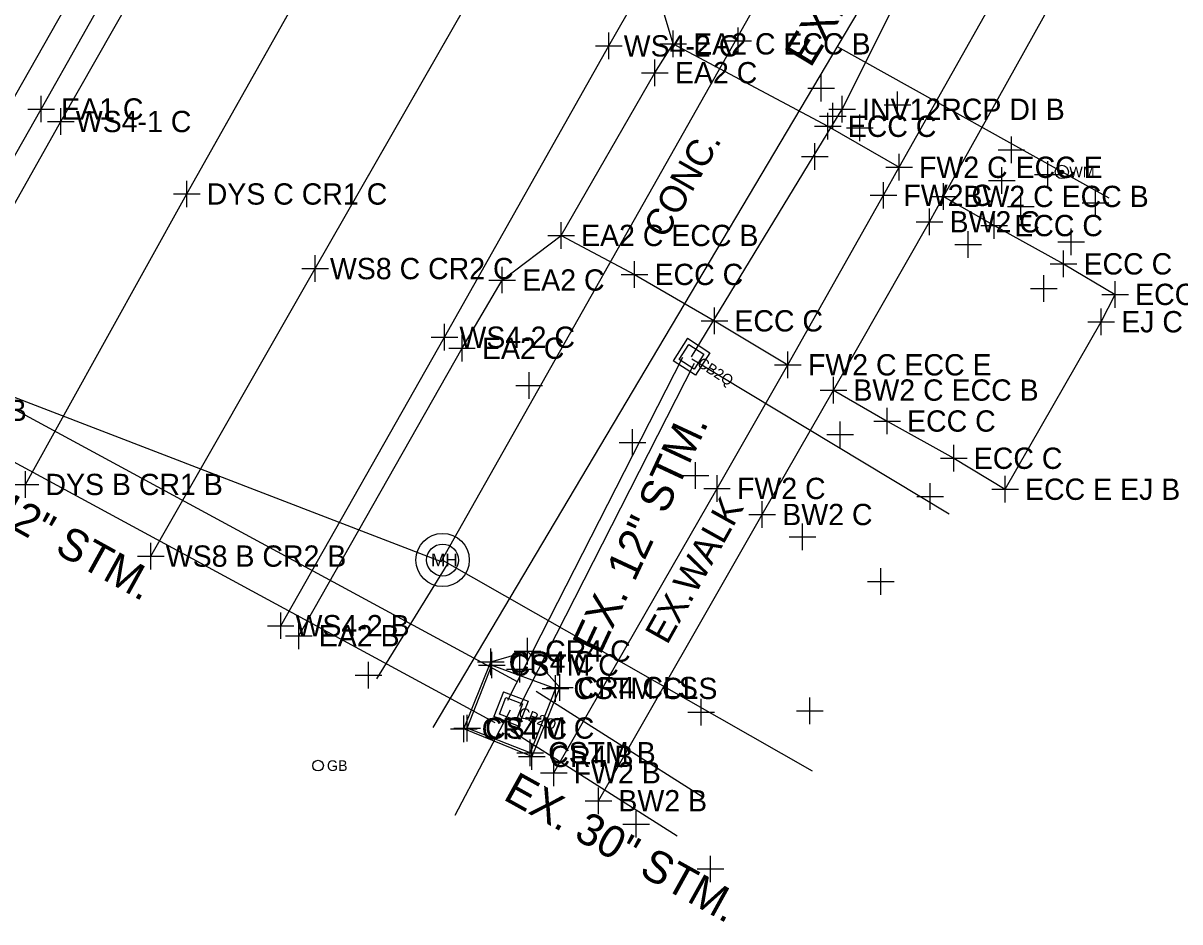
# Model space of a CAD drawing. Extents: x 1363693 to 1365209, y 422201 to 424153.
# Drawn here: x 1364063.7 to 1364150.5, y 422675.6 to 422743.1 of the extents above; entities that cross this region are included whole.
import ezdxf

# ---------------------------------------------------------------- set-up
doc = ezdxf.new("R2010")
doc.units = 0
for name, color, linetype in [('DR_X_Cells', 7, 'Continuous'), ('DR_X_Ditch', 7, 'Continuous'), ('DR_X_Storm_Sewer', 7, 'Continuous'), ('DR_X_Text', 7, 'Continuous'), ('O-ALGN-BASELINE-WERK-CL-RW', 7, 'Continuous'), ('O-ALGN-TEXT-BASELINE-WERK-CL-RW', 7, 'Continuous'), ('OWNERS', 7, 'Continuous'), ('PM_X_Channelizing_Line', 7, 'Continuous'), ('PM_X_CL_Double_Solid', 7, 'Continuous'), ('PM_X_Edge_Line', 7, 'Continuous'), ('PV_X_Driveway', 7, 'Continuous'), ('PV_X_Joint', 7, 'Continuous'), ('RD_X_Text', 7, 'Continuous'), ('SV_X_Original_Ground', 7, 'Continuous'), ('SV_X_Shot_Marker', 7, 'Continuous'), ('UT_X_Gas', 7, 'Continuous'), ('UT_X_Gas_Cells', 7, 'Continuous'), ('UT_X_Gas_Text', 7, 'Continuous'), ('UT_X_Sanitary_Line', 7, 'Continuous'), ('UT_X_Unknown_Cells', 7, 'Continuous'), ('UT_X_Water', 7, 'Continuous'), ('UT_X_Water_Text', 7, 'Continuous')]:
    doc.layers.add(name, color=color, linetype=linetype)

msp = doc.modelspace()

# ---------------------------------------------------------------- linework, layer by layer
at = {"layer": 'DR_X_Cells'}
for p, q in [((1364113.567, 422719.415), (1364112.486, 422717.732)), ((1364112.947, 422717.833), (1364113.668, 422718.954)), ((1364113.567, 422719.415), (1364115.25, 422718.334)), ((1364113.668, 422718.954), (1364114.789, 422718.233)), ((1364114.789, 422718.233), (1364114.068, 422717.112)), ((1364115.25, 422718.334), (1364114.169, 422716.651)), ((1364114.169, 422716.651), (1364112.486, 422717.732)), ((1364114.068, 422717.112), (1364112.947, 422717.833)), ((1364097.036, 422690.156), (1364098.876, 422694.888)), ((1364097.036, 422690.156), (1364098.876, 422694.888)), ((1364098.876, 422694.888), (1364103.664, 422693.131)), ((1364098.876, 422694.888), (1364103.664, 422693.131)), ((1364099.75, 422692.884), (1364099.027, 422691.019)), ((1364099.75, 422692.884), (1364101.615, 422692.161)), ((1364103.664, 422693.131), (1364101.763, 422688.305)), ((1364103.664, 422693.131), (1364101.763, 422688.305)), ((1364099.458, 422691.209), (1364099.94, 422692.453)), ((1364099.94, 422692.453), (1364101.184, 422691.971)), ((1364101.615, 422692.161), (1364100.892, 422690.296)), ((1364100.702, 422690.727), (1364099.458, 422691.209)), ((1364101.184, 422691.971), (1364100.702, 422690.727)), ((1364100.892, 422690.296), (1364099.027, 422691.019)), ((1364101.763, 422688.305), (1364097.036, 422690.156)), ((1364101.763, 422688.305), (1364097.036, 422690.156))]:
    msp.add_line(p, q, dxfattribs=at)
at = {"layer": 'DR_X_Ditch'}
msp.add_line((1364125.178, 422736.61), (1364134.344, 422754.934), dxfattribs=at)
msp.add_line((1364125.178, 422736.61), (1364134.344, 422754.934), dxfattribs=at)
at = {"layer": 'DR_X_Storm_Sewer'}
for p, q in [((1364113.868, 422718.033), (1364125.178, 422736.61)), ((1364113.868, 422718.033), (1364125.178, 422736.61)), ((1364100.795, 422693.619), (1364024.115, 422735.165)), ((1364099.127, 422690.541), (1364022.447, 422732.088)), ((1364100.084, 422692.257), (1364113.216, 422717.999)), ((1364100.975, 422691.802), (1364114.107, 422717.544)), ((1364113.889, 422717.883), (1364133.223, 422706.238)), ((1364102.199, 422692.922), (1364114.661, 422685.011)), ((1364100.257, 422691.508), (1364096.103, 422683.598)), ((1364100.324, 422689.967), (1364112.786, 422682.056))]:
    msp.add_line(p, q, dxfattribs=at)
at = {"layer": 'O-ALGN-BASELINE-WERK-CL-RW'}
for points in [[(1364063.861, 422708.444), (1364075.973, 422730.252), (1364088.269, 422752.078), (1364100.636, 422773.911), (1364112.961, 422795.674), (1364125.29, 422817.23)], [(1364073.278, 422703.065), (1364085.603, 422724.652), (1364098.051, 422746.39), (1364110.44, 422768.276), (1364122.785, 422790.021), (1364135.008, 422811.616)], [(1364101.874, 422688.026), (1364096.778, 422690.099), (1364098.805, 422695.12), (1364101.546, 422695.933), (1364103.975, 422693.194), (1364101.874, 422688.026)]]:
    msp.add_lwpolyline(points, dxfattribs=at)
at = {"layer": 'O-ALGN-TEXT-BASELINE-WERK-CL-RW'}
for points in [[(1364106.881, 422684.697), (1364119.186, 422706.188), (1364124.526, 422715.531), (1364131.747, 422728.163), (1364132.791, 422730.069), (1364143.66, 422749.553), (1364152.461, 422765.008), (1364156.109, 422771.56), (1364160.497, 422779.388), (1364168.274, 422793.373), (1364180.613, 422814.721), (1364181.642, 422816.657), (1364190.312, 422832.027), (1364193.051, 422836.798), (1364205.158, 422858.42), (1364210.927, 422868.703), (1364217.538, 422880.583), (1364219, 422883.263), (1364226.216, 422896.876), (1364226.216, 422896.876), (1364230.124, 422904.765), (1364230.124, 422904.765), (1364238.068, 422921.555)], [(1364103.528, 422686.802), (1364115.786, 422708.146), (1364121.111, 422717.426), (1364128.281, 422730.151), (1364129.454, 422732.257), (1364140.312, 422751.513), (1364149.061, 422767.123), (1364152.636, 422773.448), (1364157.186, 422781.325), (1364164.964, 422795.393), (1364177.23, 422816.837)]]:
    msp.add_lwpolyline(points, dxfattribs=at)
at = {"layer": 'OWNERS'}
for points in [[(1364084.38, 422697.084), (1364096.639, 422718.672), (1364099.659, 422723.794), (1364104.078, 422727.14), (1364111.127, 422739.357), (1364112.498, 422741.524), (1364111.547, 422744.697), (1364121.455, 422762.22), (1364129.492, 422775.694), (1364132.238, 422776.536), (1364135.676, 422782.955), (1364140.445, 422791.159), (1364139.16, 422793.068), (1364146.3, 422805.509)], [(1364052.728, 422714.955), (1364065.039, 422736.632), (1364077.353, 422758.456), (1364089.632, 422780.271), (1364102.08, 422801.911)], [(1364112.498, 422741.524), (1364124.101, 422735.336), (1364129.454, 422732.257)], [(1364104.078, 422727.14), (1364109.597, 422724.214), (1364115.589, 422720.729), (1364121.111, 422717.426)]]:
    msp.add_lwpolyline(points, dxfattribs=at)
at = {"layer": 'PM_X_Channelizing_Line'}
for p, q in [((1364107.662, 422741.373), (1364120.011, 422763.024)), ((1364066.522, 422735.694), (1364078.931, 422757.548)), ((1364075.973, 422730.252), (1364088.269, 422752.078)), ((1364085.603, 422724.652), (1364098.051, 422746.39)), ((1364085.603, 422724.652), (1364098.051, 422746.39)), ((1364095.324, 422719.498), (1364107.662, 422741.373)), ((1364054.279, 422714.005), (1364066.522, 422735.694)), ((1364063.861, 422708.444), (1364075.973, 422730.252)), ((1364073.278, 422703.065), (1364085.603, 422724.652)), ((1364073.278, 422703.065), (1364085.603, 422724.652)), ((1364083.023, 422697.841), (1364095.324, 422719.498))]:
    msp.add_line(p, q, dxfattribs=at)
at = {"layer": 'PM_X_CL_Double_Solid'}
for p, q in [((1364075.973, 422730.252), (1364088.269, 422752.078)), ((1364063.861, 422708.444), (1364075.973, 422730.252))]:
    msp.add_line(p, q, dxfattribs=at)
at = {"layer": 'PM_X_Edge_Line'}
for p, q in [((1364107.662, 422741.373), (1364120.011, 422763.024)), ((1364066.522, 422735.694), (1364078.931, 422757.548)), ((1364095.324, 422719.498), (1364107.662, 422741.373)), ((1364054.279, 422714.005), (1364066.522, 422735.694)), ((1364083.023, 422697.841), (1364095.324, 422719.498))]:
    msp.add_line(p, q, dxfattribs=at)
at = {"layer": 'PV_X_Driveway'}
for points in [[(1364132.791, 422730.069), (1364136.606, 422727.882), (1364141.808, 422725.007), (1364145.678, 422722.714)], [(1364124.526, 422715.531), (1364128.554, 422713.207), (1364133.565, 422710.411), (1364137.414, 422708.085)]]:
    msp.add_lwpolyline(points, dxfattribs=at)
at = {"layer": 'PV_X_Joint'}
for p, q in [((1364144.635, 422720.662), (1364145.678, 422722.714)), ((1364137.414, 422708.085), (1364144.635, 422720.662))]:
    msp.add_line(p, q, dxfattribs=at)
at = {"layer": 'SV_X_Original_Ground'}
for p, q in [((1364107.662, 422740.373), (1364107.662, 422742.373)), ((1364117.383, 422740.762), (1364117.383, 422742.762)), ((1364116.383, 422741.762), (1364118.383, 422741.762)), ((1364106.662, 422741.373), (1364108.662, 422741.373)), ((1364123.617, 422737.204), (1364123.617, 422739.204)), ((1364122.617, 422738.204), (1364124.617, 422738.204)), ((1364129.331, 422735.947), (1364129.331, 422737.947)), ((1364066.522, 422734.694), (1364066.522, 422736.694)), ((1364124.477, 422735.103), (1364124.477, 422737.103)), ((1364128.331, 422736.947), (1364130.331, 422736.947)), ((1364065.522, 422735.694), (1364067.522, 422735.694)), ((1364123.477, 422736.103), (1364125.477, 422736.103)), ((1364126.511, 422734.23), (1364126.511, 422736.23)), ((1364125.511, 422735.23), (1364127.511, 422735.23)), ((1364137.886, 422732.558), (1364137.886, 422734.558)), ((1364123.135, 422732.065), (1364123.135, 422734.065)), ((1364122.135, 422733.065), (1364124.135, 422733.065)), ((1364136.886, 422733.558), (1364138.886, 422733.558)), ((1364137.178, 422730.267), (1364137.178, 422732.267)), ((1364140.637, 422730.704), (1364140.637, 422732.704)), ((1364075.973, 422729.252), (1364075.973, 422731.252)), ((1364136.178, 422731.267), (1364138.178, 422731.267)), ((1364139.637, 422731.704), (1364141.637, 422731.704)), ((1364074.973, 422730.252), (1364076.973, 422730.252)), ((1364138.603, 422728.306), (1364138.603, 422730.306)), ((1364144.2, 422728.59), (1364144.2, 422730.59)), ((1364143.2, 422729.59), (1364145.2, 422729.59)), ((1364137.603, 422729.306), (1364139.603, 422729.306)), ((1364142.375, 422725.654), (1364142.375, 422727.654)), ((1364134.634, 422725.454), (1364134.634, 422727.454)), ((1364133.634, 422726.454), (1364135.634, 422726.454)), ((1364141.375, 422726.654), (1364143.375, 422726.654)), ((1364085.603, 422723.652), (1364085.603, 422725.652)), ((1364084.603, 422724.652), (1364086.603, 422724.652)), ((1364140.317, 422722.148), (1364140.317, 422724.148)), ((1364139.317, 422723.148), (1364141.317, 422723.148)), ((1364095.324, 422718.498), (1364095.324, 422720.498)), ((1364094.324, 422719.498), (1364096.324, 422719.498)), ((1364101.674, 422714.871), (1364101.674, 422716.871)), ((1364100.674, 422715.871), (1364102.674, 422715.871)), ((1364125.024, 422711.182), (1364125.024, 422713.182)), ((1364109.44, 422710.589), (1364109.44, 422712.589)), ((1364124.024, 422712.182), (1364126.024, 422712.182)), ((1364108.44, 422711.589), (1364110.44, 422711.589)), ((1364063.861, 422707.444), (1364063.861, 422709.444)), ((1364114.182, 422708.125), (1364114.182, 422710.125)), ((1364113.182, 422709.125), (1364115.182, 422709.125)), ((1364131.791, 422706.542), (1364131.791, 422708.542)), ((1364062.861, 422708.444), (1364064.861, 422708.444)), ((1364130.791, 422707.542), (1364132.791, 422707.542)), ((1364122.196, 422703.52), (1364122.196, 422705.52)), ((1364121.196, 422704.52), (1364123.196, 422704.52)), ((1364073.278, 422702.065), (1364073.278, 422704.065)), ((1364072.278, 422703.065), (1364074.278, 422703.065)), ((1364128.095, 422700.158), (1364128.095, 422702.158)), ((1364127.095, 422701.158), (1364129.095, 422701.158)), ((1364083.023, 422696.841), (1364083.023, 422698.841)), ((1364082.023, 422697.841), (1364084.023, 422697.841)), ((1364101.546, 422694.933), (1364101.546, 422696.933)), ((1364098.805, 422694.12), (1364098.805, 422696.12)), ((1364100.546, 422695.933), (1364102.546, 422695.933)), ((1364100.985, 422693.583), (1364100.985, 422695.583)), ((1364089.61, 422693.122), (1364089.61, 422695.122)), ((1364097.805, 422695.12), (1364099.805, 422695.12)), ((1364088.61, 422694.122), (1364090.61, 422694.122)), ((1364099.985, 422694.583), (1364101.985, 422694.583)), ((1364103.975, 422692.194), (1364103.975, 422694.194)), ((1364102.975, 422693.194), (1364104.975, 422693.194)), ((1364114.587, 422690.341), (1364114.587, 422692.341)), ((1364122.757, 422690.441), (1364122.757, 422692.441)), ((1364113.587, 422691.341), (1364115.587, 422691.341)), ((1364121.757, 422691.441), (1364123.757, 422691.441)), ((1364096.778, 422689.099), (1364096.778, 422691.099)), ((1364095.778, 422690.099), (1364097.778, 422690.099)), ((1364101.874, 422687.026), (1364101.874, 422689.026)), ((1364100.874, 422688.026), (1364102.874, 422688.026)), ((1364109.724, 422681.928), (1364109.724, 422683.928)), ((1364108.724, 422682.928), (1364110.724, 422682.928)), ((1364115.298, 422678.573), (1364115.298, 422680.573)), ((1364114.298, 422679.573), (1364116.298, 422679.573))]:
    msp.add_line(p, q, dxfattribs=at)
at = {"layer": 'SV_X_Shot_Marker'}
for p, q in [((1364112.498, 422740.524), (1364112.498, 422742.524)), ((1364111.498, 422741.524), (1364113.498, 422741.524)), ((1364111.127, 422738.357), (1364111.127, 422740.357)), ((1364110.127, 422739.357), (1364112.127, 422739.357)), ((1364065.039, 422735.632), (1364065.039, 422737.632)), ((1364125.178, 422735.61), (1364125.178, 422737.61)), ((1364064.039, 422736.632), (1364066.039, 422736.632)), ((1364124.101, 422734.336), (1364124.101, 422736.336)), ((1364124.178, 422736.61), (1364126.178, 422736.61)), ((1364123.101, 422735.336), (1364125.101, 422735.336)), ((1364129.454, 422731.257), (1364129.454, 422733.257)), ((1364128.454, 422732.257), (1364130.454, 422732.257)), ((1364128.281, 422729.151), (1364128.281, 422731.151)), ((1364132.791, 422729.069), (1364132.791, 422731.069)), ((1364127.281, 422730.151), (1364129.281, 422730.151)), ((1364131.791, 422730.069), (1364133.791, 422730.069)), ((1364131.747, 422727.163), (1364131.747, 422729.163)), ((1364136.606, 422726.882), (1364136.606, 422728.882)), ((1364104.078, 422726.14), (1364104.078, 422728.14)), ((1364130.747, 422728.163), (1364132.747, 422728.163)), ((1364135.606, 422727.882), (1364137.606, 422727.882)), ((1364103.078, 422727.14), (1364105.078, 422727.14)), ((1364141.808, 422724.007), (1364141.808, 422726.007)), ((1364109.597, 422723.214), (1364109.597, 422725.214)), ((1364140.808, 422725.007), (1364142.808, 422725.007)), ((1364099.659, 422722.794), (1364099.659, 422724.794)), ((1364108.597, 422724.214), (1364110.597, 422724.214)), ((1364098.659, 422723.794), (1364100.659, 422723.794)), ((1364145.678, 422721.714), (1364145.678, 422723.714)), ((1364144.678, 422722.714), (1364146.678, 422722.714)), ((1364115.589, 422719.729), (1364115.589, 422721.729)), ((1364144.635, 422719.662), (1364144.635, 422721.662)), ((1364114.589, 422720.729), (1364116.589, 422720.729)), ((1364143.635, 422720.662), (1364145.635, 422720.662)), ((1364096.639, 422717.672), (1364096.639, 422719.672)), ((1364095.639, 422718.672), (1364097.639, 422718.672)), ((1364121.111, 422716.426), (1364121.111, 422718.426)), ((1364120.111, 422717.426), (1364122.111, 422717.426)), ((1364124.526, 422714.531), (1364124.526, 422716.531)), ((1364123.526, 422715.531), (1364125.526, 422715.531)), ((1364128.554, 422712.207), (1364128.554, 422714.207)), ((1364127.554, 422713.207), (1364129.554, 422713.207)), ((1364133.565, 422709.411), (1364133.565, 422711.411)), ((1364132.565, 422710.411), (1364134.565, 422710.411)), ((1364115.786, 422707.146), (1364115.786, 422709.146)), ((1364137.414, 422707.085), (1364137.414, 422709.085)), ((1364114.786, 422708.146), (1364116.786, 422708.146)), ((1364136.414, 422708.085), (1364138.414, 422708.085)), ((1364119.186, 422705.188), (1364119.186, 422707.188)), ((1364118.186, 422706.188), (1364120.186, 422706.188)), ((1364084.38, 422696.084), (1364084.38, 422698.084)), ((1364083.38, 422697.084), (1364085.38, 422697.084)), ((1364098.876, 422693.888), (1364098.876, 422695.888)), ((1364097.876, 422694.888), (1364099.876, 422694.888)), ((1364103.664, 422692.131), (1364103.664, 422694.131)), ((1364102.664, 422693.131), (1364104.664, 422693.131)), ((1364097.036, 422689.156), (1364097.036, 422691.156)), ((1364096.036, 422690.156), (1364098.036, 422690.156)), ((1364101.763, 422687.305), (1364101.763, 422689.305)), ((1364100.763, 422688.305), (1364102.763, 422688.305)), ((1364103.528, 422685.802), (1364103.528, 422687.802)), ((1364102.528, 422686.802), (1364104.528, 422686.802)), ((1364106.881, 422683.697), (1364106.881, 422685.697)), ((1364105.881, 422684.697), (1364107.881, 422684.697))]:
    msp.add_line(p, q, dxfattribs=at)
at = {"layer": 'UT_X_Gas'}
msp.add_lwpolyline([(1364207.557, 423089.372), (1364211.518, 423072.856), (1364208.943, 423046.381), (1364201.649, 423012.485), (1364191.712, 422981.617), (1364181.14, 422953.292), (1364166.466, 422921.961), (1364127.708, 422851.525), (1364051.86, 422717.903)], dxfattribs=at)
at = {"layer": 'UT_X_Gas_Cells'}
msp.add_circle((1364085.831, 422687.332), 0.4, dxfattribs=at)
at = {"layer": 'UT_X_Sanitary_Line'}
for p, q in [((1364095.507, 422702.416), (1364090.23, 422693.852)), ((1364095.182, 422702.77), (1364122.943, 422686.931))]:
    msp.add_line(p, q, dxfattribs=at)
msp.add_lwpolyline([(1364014.261, 422733.758), (1364095.069, 422702.67), (1364258.083, 422991.019), (1364292.624, 423022.755)], dxfattribs=at)
at = {"layer": 'UT_X_Unknown_Cells'}
for radius in [2, 1.2]:
    msp.add_circle((1364095.182, 422702.77), radius, dxfattribs=at)
at = {"layer": 'UT_X_Water'}
msp.add_line((1364145.23, 422729.926), (1364124.825, 422741.303), dxfattribs=at)
msp.add_lwpolyline([(1364263.889, 423134.469), (1364270.338, 423133.178), (1364266, 423070.885), (1364241.238, 422967.415), (1364211.801, 422898.599), (1364139.416, 422765.962), (1364094.46, 422690.2)], dxfattribs=at)
for points in [[(1364141.564, 422731.975), (1364141.679, 422731.908), (1364141.679, 422731.908), (1364141.546, 422731.908)], [(1364141.612, 422732.023), (1364141.679, 422731.908), (1364141.679, 422731.908), (1364141.564, 422731.975)], [(1364141.679, 422732.041), (1364141.679, 422731.908), (1364141.679, 422731.908), (1364141.612, 422732.023)], [(1364141.746, 422732.023), (1364141.679, 422731.908), (1364141.679, 422731.908), (1364141.679, 422732.041)], [(1364141.794, 422731.975), (1364141.679, 422731.908), (1364141.679, 422731.908), (1364141.746, 422732.023)], [(1364141.812, 422731.908), (1364141.679, 422731.908), (1364141.679, 422731.908), (1364141.794, 422731.975)], [(1364141.546, 422731.908), (1364141.679, 422731.908), (1364141.679, 422731.908), (1364141.564, 422731.841)], [(1364141.564, 422731.841), (1364141.679, 422731.908), (1364141.679, 422731.908), (1364141.612, 422731.793)], [(1364141.612, 422731.793), (1364141.679, 422731.908), (1364141.679, 422731.908), (1364141.679, 422731.775)], [(1364141.679, 422731.775), (1364141.679, 422731.908), (1364141.679, 422731.908), (1364141.746, 422731.793)], [(1364141.746, 422731.793), (1364141.679, 422731.908), (1364141.679, 422731.908), (1364141.794, 422731.841)], [(1364141.794, 422731.841), (1364141.679, 422731.908), (1364141.679, 422731.908), (1364141.812, 422731.908)]]:
    msp.add_lwpolyline(points, close=True, dxfattribs=at)
msp.add_circle((1364141.679, 422731.908), 0.5, dxfattribs=at)

# ---------------------------------------------------------------- texts
at = {"layer": 'DR_X_Text'}
for s, height, rotation, p in [('CB2Q', 0.8, 327.2757, (1364114.235, 422717.367)), ('EX. 12" STM.', 2.4, 65.02467, (1364107.019, 422695.563)), ('EX. 42" STM.', 2.4, 330.99667, (1364055.765, 422709.014)), ('CB2Q', 0.8, 338.81126, (1364100.813, 422691.011)), ('EX. 30" STM.', 2.4, 330.99667, (1364099.643, 422684.835))]:
    msp.add_text(s, height=height, rotation=rotation, dxfattribs=at).set_placement(p)
at = {"layer": 'RD_X_Text'}
for s, rotation, p in [('CONC.', 60.281, (1364111.898, 422726.814)), ('EX.WALK', 60.80754, (1364112.041, 422696.344))]:
    msp.add_text(s, height=2, rotation=rotation, dxfattribs=at).set_placement(p)
at = {"layer": 'SV_X_Original_Ground'}
for s, p in [('WS4-2 C', (1364108.781, 422740.573)), ('WS4-1 C', (1364067.641, 422734.894)), ('DYS C CR1 C', (1364077.473, 422729.452)), ('WS8 C CR2 C', (1364086.722, 422723.852)), ('WS4-2 C', (1364096.443, 422718.698)), ('WS4-1 B', (1364055.398, 422713.205)), ('DYS B CR1 B', (1364065.361, 422707.644)), ('WS8 B CR2 B', (1364074.397, 422702.265)), ('WS4-2 B', (1364084.142, 422697.041)), ('CR4 C', (1364102.883, 422695.133)), ('CR4 C', (1364100.142, 422694.32)), ('CR4 CLS', (1364105.312, 422692.394)), ('CR4 C', (1364098.115, 422689.299)), ('CR4 B', (1364103.211, 422687.226))]:
    msp.add_text(s, height=1.6, dxfattribs=at).set_placement(p)
at = {"layer": 'SV_X_Shot_Marker'}
for s, p in [('EA2 C ECC B', (1364113.998, 422740.724)), ('EA2 C', (1364112.627, 422738.557)), ('EA1 C', (1364066.539, 422735.832)), ('INV12RCP DI B', (1364126.678, 422735.81)), ('ECC C', (1364125.601, 422734.536)), ('FW2 C ECC E', (1364130.954, 422731.457)), ('FW2 C', (1364129.781, 422729.351)), ('BW2 C ECC B', (1364134.291, 422729.269)), ('BW2 C', (1364133.247, 422727.363)), ('ECC C', (1364138.106, 422727.082)), ('EA2 C ECC B', (1364105.578, 422726.34)), ('ECC C', (1364111.097, 422723.414)), ('ECC C', (1364143.308, 422724.207)), ('EA2 C', (1364101.159, 422722.994)), ('ECC E EJ E', (1364147.178, 422721.914)), ('ECC C', (1364117.089, 422719.929)), ('EJ C', (1364146.135, 422719.862)), ('EA2 C', (1364098.139, 422717.872)), ('FW2 C ECC E', (1364122.611, 422716.626)), ('BW2 C ECC B', (1364126.026, 422714.731)), ('ECC C', (1364130.054, 422712.407)), ('ECC C', (1364135.065, 422709.611)), ('FW2 C', (1364117.286, 422707.346)), ('ECC E EJ B', (1364138.914, 422707.285)), ('BW2 C', (1364120.686, 422705.388)), ('EA2 B', (1364085.88, 422696.284)), ('CSTM C', (1364100.213, 422694.088)), ('CSTM CLS', (1364105.001, 422692.331)), ('CSTM C', (1364098.373, 422689.356)), ('CSTM B', (1364103.1, 422687.505)), ('FW2 B', (1364105.028, 422686.002)), ('BW2 B', (1364108.381, 422683.897))]:
    msp.add_text(s, height=1.6, dxfattribs=at).set_placement(p)
at = {"layer": 'UT_X_Gas_Text'}
msp.add_text('GB', height=0.8, dxfattribs=at).set_placement((1364086.499, 422686.932))
at = {"layer": 'UT_X_Unknown_Cells'}
msp.add_text('MH', height=0.96, dxfattribs=at).set_placement((1364094.313, 422702.29))
at = {"layer": 'UT_X_Water_Text'}
msp.add_text('EX. 8" WM', height=2.4, rotation=58.87031, dxfattribs=at).set_placement((1364122.806, 422739.656))
msp.add_text('WM', height=0.8, dxfattribs=at).set_placement((1364142.239, 422731.508))

doc.saveas('drawing.dxf')
